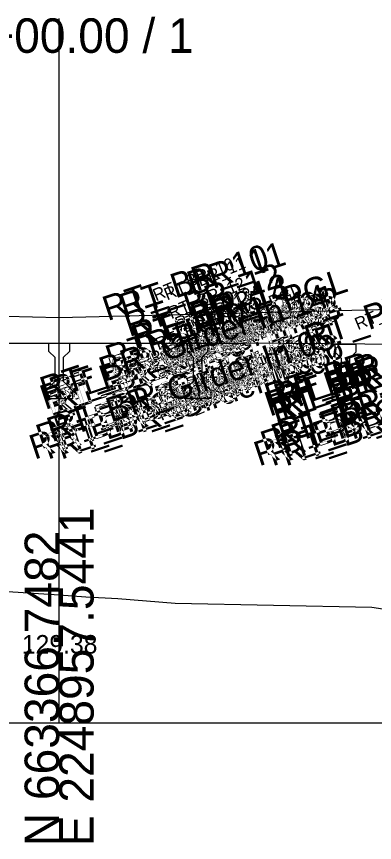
# Model space of a CAD drawing. Extents: x -26 to 2603, y -10 to 9566.
# Drawn here: x 1296.5 to 1325.6, y 3990.3 to 4057.3 of the extents above; entities that cross this region are included whole.
import ezdxf

# ---------------------------------------------------------------- set-up
doc = ezdxf.new("R2010")
doc.units = 0
for name, color, linetype in [('Exist Cross Section Cell', 7, 'Continuous'), ('Exist XS Center Line Elevation Label', 7, 'Continuous'), ('Exist XS Ground Line', 7, 'Continuous'), ('Prop CMT Concrete Structures', 7, 'Continuous'), ('Prop XS SE Text', 7, 'Continuous'), ('Scratch_Level_9', 7, 'Continuous')]:
    doc.layers.add(name, color=color, linetype=linetype)

msp = doc.modelspace()

# ---------------------------------------------------------------- linework, layer by layer
at = {"layer": 'Exist Cross Section Cell'}
for p, q in [((1300, 4000), (1300, 4057.156)), ((1000, 4000), (1300, 4000)), ((1300, 4000), (1600, 4000))]:
    msp.add_line(p, q, dxfattribs=at)
at = {"layer": 'Exist XS Ground Line'}
for p, q in [((1285.279, 4011.348), (1300, 4010.382)), ((1300, 4010.382), (1302.173, 4010.24)), ((1302.173, 4010.24), (1304.766, 4010.11)), ((1304.766, 4010.11), (1309.415, 4009.714)), ((1309.415, 4009.714), (1325.377, 4009.386)), ((1325.377, 4009.386), (1332.898, 4008.324))]:
    msp.add_line(p, q, dxfattribs=at)
at = {"layer": 'Prop CMT Concrete Structures'}
for points in [[(1299.98, 4032.865), (1284.98, 4033.24), (1272.98, 4033.54)], [(1299.98, 4032.865), (1284.98, 4033.24), (1272.98, 4033.54)], [(1299.98, 4032.865), (1284.98, 4033.24), (1272.98, 4033.54)], [(1327.003, 4033.541), (1300, 4032.866)], [(1327.003, 4033.541), (1300, 4032.866)], [(1327.003, 4033.541), (1300, 4032.866)], [(1256.499, 4030.803), (1261, 4030.803), (1285, 4030.803), (1315, 4030.803)], [(1256.499, 4030.803), (1261, 4030.803), (1285, 4030.803), (1315, 4030.803)], [(1256.499, 4030.803), (1261, 4030.803), (1285, 4030.803), (1315, 4030.803)], [(1299.167, 4030.136), (1299.167, 4030.81)], [(1299.167, 4030.81), (1300, 4030.803), (1300.833, 4030.796)], [(1299.167, 4030.136), (1299.167, 4030.81)], [(1299.167, 4030.81), (1300, 4030.803), (1300.833, 4030.796)], [(1299.167, 4030.136), (1299.167, 4030.81)], [(1299.167, 4030.81), (1300, 4030.803), (1300.833, 4030.796)], [(1300.833, 4030.796), (1300.833, 4030.136)], [(1300.833, 4030.796), (1300.833, 4030.136)], [(1300.833, 4030.796), (1300.833, 4030.136)], [(1310.41, 4030.143), (1310.41, 4030.817)], [(1310.41, 4030.817), (1311.243, 4030.81), (1312.076, 4030.803)], [(1310.41, 4030.143), (1310.41, 4030.817)], [(1310.41, 4030.817), (1311.243, 4030.81), (1312.076, 4030.803)], [(1310.41, 4030.143), (1310.41, 4030.817)], [(1310.41, 4030.817), (1311.243, 4030.81), (1312.076, 4030.803)], [(1312.076, 4030.803), (1312.076, 4030.143)], [(1312.076, 4030.803), (1312.076, 4030.143)], [(1312.076, 4030.803), (1312.076, 4030.143)], [(1385.145, 4030.219), (1351, 4030.503), (1315, 4030.803), (1315, 4030.803)], [(1385.145, 4030.219), (1351, 4030.503), (1315, 4030.803), (1315, 4030.803)], [(1386.501, 4030.207), (1351, 4030.503), (1315, 4030.803), (1315, 4030.803)], [(1322.41, 4030.741), (1323.243, 4030.734), (1324.076, 4030.727)], [(1322.41, 4030.068), (1322.41, 4030.741)], [(1322.41, 4030.741), (1323.243, 4030.734), (1324.076, 4030.727)], [(1322.41, 4030.068), (1322.41, 4030.741)], [(1322.41, 4030.741), (1323.243, 4030.734), (1324.076, 4030.727)], [(1322.41, 4030.068), (1322.41, 4030.741)], [(1324.076, 4030.727), (1324.076, 4030.068)], [(1324.076, 4030.727), (1324.076, 4030.068)], [(1324.076, 4030.727), (1324.076, 4030.068)], [(1299.667, 4029.636), (1299.167, 4030.136)], [(1299.667, 4029.636), (1299.167, 4030.136)], [(1299.667, 4029.636), (1299.167, 4030.136)], [(1300.833, 4030.136), (1300.333, 4029.636)], [(1300.833, 4030.136), (1300.333, 4029.636)], [(1300.833, 4030.136), (1300.333, 4029.636)], [(1310.91, 4029.643), (1310.41, 4030.143)], [(1310.91, 4029.643), (1310.41, 4030.143)], [(1310.91, 4029.643), (1310.41, 4030.143)], [(1312.076, 4030.143), (1311.576, 4029.643)], [(1312.076, 4030.143), (1311.576, 4029.643)], [(1312.076, 4030.143), (1311.576, 4029.643)], [(1322.91, 4029.568), (1322.41, 4030.068)], [(1322.91, 4029.568), (1322.41, 4030.068)], [(1322.91, 4029.568), (1322.41, 4030.068)], [(1324.076, 4030.068), (1323.576, 4029.568)], [(1324.076, 4030.068), (1323.576, 4029.568)], [(1324.076, 4030.068), (1323.576, 4029.568)], [(1299.667, 4027.72), (1299.667, 4029.636)], [(1299.667, 4027.72), (1299.667, 4029.636)], [(1299.667, 4027.72), (1299.667, 4029.636)], [(1300.333, 4029.636), (1300.333, 4027.72)], [(1300.333, 4029.636), (1300.333, 4027.72)], [(1300.333, 4029.636), (1300.333, 4027.72)], [(1310.91, 4027.727), (1310.91, 4029.643)], [(1310.91, 4027.727), (1310.91, 4029.643)], [(1310.91, 4027.727), (1310.91, 4029.643)], [(1311.576, 4029.643), (1311.576, 4027.727)], [(1311.576, 4029.643), (1311.576, 4027.727)], [(1311.576, 4029.643), (1311.576, 4027.727)], [(1322.91, 4027.651), (1322.91, 4029.568)], [(1322.91, 4027.651), (1322.91, 4029.568)], [(1322.91, 4027.651), (1322.91, 4029.568)], [(1323.576, 4029.568), (1323.576, 4027.651)], [(1323.576, 4029.568), (1323.576, 4027.651)], [(1323.576, 4029.568), (1323.576, 4027.651)], [(1298.917, 4026.97), (1299.667, 4027.72)], [(1298.917, 4026.97), (1299.667, 4027.72)], [(1298.917, 4026.97), (1299.667, 4027.72)], [(1300.333, 4027.72), (1301.083, 4026.97)], [(1300.333, 4027.72), (1301.083, 4026.97)], [(1300.333, 4027.72), (1301.083, 4026.97)], [(1310.16, 4026.977), (1310.91, 4027.727)], [(1310.16, 4026.977), (1310.91, 4027.727)], [(1310.16, 4026.977), (1310.91, 4027.727)], [(1311.576, 4027.727), (1312.326, 4026.977)], [(1311.576, 4027.727), (1312.326, 4026.977)], [(1311.576, 4027.727), (1312.326, 4026.977)], [(1322.16, 4026.901), (1322.91, 4027.651)], [(1322.16, 4026.901), (1322.91, 4027.651)], [(1322.16, 4026.901), (1322.91, 4027.651)], [(1323.576, 4027.651), (1324.326, 4026.901)], [(1323.576, 4027.651), (1324.326, 4026.901)], [(1323.576, 4027.651), (1324.326, 4026.901)], [(1298.917, 4026.303), (1298.917, 4026.97)], [(1298.917, 4026.303), (1298.917, 4026.97)], [(1298.917, 4026.303), (1298.917, 4026.97)], [(1301.083, 4026.97), (1301.083, 4026.303)], [(1301.083, 4026.97), (1301.083, 4026.303)], [(1301.083, 4026.97), (1301.083, 4026.303)], [(1310.16, 4026.31), (1310.16, 4026.977)], [(1310.16, 4026.31), (1310.16, 4026.977)], [(1310.16, 4026.31), (1310.16, 4026.977)], [(1312.326, 4026.977), (1312.326, 4026.31)], [(1312.326, 4026.977), (1312.326, 4026.31)], [(1312.326, 4026.977), (1312.326, 4026.31)], [(1322.16, 4026.234), (1322.16, 4026.901)], [(1322.16, 4026.234), (1322.16, 4026.901)], [(1322.16, 4026.234), (1322.16, 4026.901)], [(1324.326, 4026.901), (1324.326, 4026.234)], [(1324.326, 4026.901), (1324.326, 4026.234)], [(1324.326, 4026.901), (1324.326, 4026.234)], [(1301.083, 4026.303), (1300, 4026.303), (1298.917, 4026.303)], [(1301.083, 4026.303), (1300, 4026.303), (1298.917, 4026.303)], [(1301.083, 4026.303), (1300, 4026.303), (1298.917, 4026.303)], [(1312.326, 4026.31), (1311.243, 4026.31), (1310.16, 4026.31)], [(1312.326, 4026.31), (1311.243, 4026.31), (1310.16, 4026.31)], [(1312.326, 4026.31), (1311.243, 4026.31), (1310.16, 4026.31)], [(1324.326, 4026.234), (1323.243, 4026.234), (1322.16, 4026.234)], [(1324.326, 4026.234), (1323.243, 4026.234), (1322.16, 4026.234)], [(1324.326, 4026.234), (1323.243, 4026.234), (1322.16, 4026.234)]]:
    msp.add_lwpolyline(points, dxfattribs=at)

# ---------------------------------------------------------------- texts
at = {"layer": 'Exist Cross Section Cell'}
msp.add_text('24+00.00 / 1', height=2.8, dxfattribs=at).set_placement((1290, 4054.356))
for s, p in [('E 2248957.5441', (1302.8, 3990)), ('N 663366.7482', (1300, 3990))]:
    msp.add_text(s, height=2.8, rotation=90, dxfattribs=at).set_placement(p)
at = {"layer": 'Exist XS Center Line Elevation Label'}
msp.add_text('129.38', height=1.5, dxfattribs=at).set_placement((1296.974, 4005.632))
at = {"layer": 'Prop XS SE Text'}
msp.add_text('0.025', height=1.5, rotation=1.4321, dxfattribs=at).set_placement((1311.486, 4033.441))
at = {"layer": 'Scratch_Level_9'}
for s, height, rotation, p in [('RT_ BR_10', 2, 18.43323, (1303.944, 4032.593)), ('RT_ BR_11', 2, 18.43323, (1305.296, 4032.797)), ('RT_ BR_10', 1, 22.55745, (1307.859, 4034.194)), ('RT_ BR_11', 1, 22.55745, (1308.769, 4034.264)), ('RT_BR_12', 2, 18.43323, (1305.702, 4031.293)), ('RT_PV1_PGL', 2, 18.43323, (1307.473, 4029.678)), ('RT_PV1_CP', 2, 18.43323, (1320.324, 4030.261)), ('RT_BR_13', 2, 18.43323, (1306.285, 4030.46)), ('RT_BR_14', 2, 18.43323, (1306.295, 4030.21)), ('RT_BR_12', 1, 22.55745, (1309.104, 4032.751)), ('RT_BR_Girder In 14', 2, 18.43323, (1298.869, 4026.065)), ('RT_BR_Girder In 01', 2, 18.43323, (1299.628, 4026.033)), ('RT_BR_Girder In 02', 2, 18.43323, (1299.923, 4025.847)), ('RT_BR_13', 1, 22.55745, (1309.672, 4031.911)), ('RT_PV1_PGL', 1, 22.55745, (1311.906, 4031.414)), ('RT_BR_Girder Mid 14', 2, 18.43323, (1317.095, 4025.52)), ('RT_BR_Girder Mid 01', 2, 18.43323, (1317.853, 4025.488)), ('RT_BR_Girder Mid 02', 2, 18.43323, (1318.149, 4025.302)), ('RT_PV1_CP', 1, 22.55745, (1324.249, 4031.857)), ('RT_BR_Girder In 13', 2, 18.43323, (1298.869, 4025.391)), ('RT_BR_Girder In 03', 2, 18.43323, (1299.923, 4025.187)), ('RT_BR_14', 1, 22.55745, (1309.667, 4031.655)), ('RT_BR_Girder Mid 13', 2, 18.43323, (1317.095, 4024.846)), ('RT_BR_Girder Mid 03', 2, 18.43323, (1318.149, 4024.642)), ('RT_BR_Girder In 12', 2, 18.43323, (1299.369, 4024.891)), ('RT_BR_Girder In 04', 2, 18.43323, (1299.423, 4024.687)), ('RT_BR_09', 2, 18.43323, (1304.182, 4028.618)), ('RT_BR_Girder In 14', 1, 22.55745, (1307.576, 4029.052)), ('RT_BR_Girder In 01', 1, 22.55745, (1308.463, 4029.067)), ('RT_BR_08', 2, 18.43323, (1308.683, 4028.581)), ('RT_BR_Girder In 02', 1, 22.55745, (1309.162, 4029.004)), ('RT_BR_Girder Mid 12', 2, 18.43323, (1317.595, 4024.346)), ('RT_BR_Girder Mid 04', 2, 18.43323, (1317.649, 4024.142)), ('RT_BR_Girder In 13', 1, 22.55745, (1307.591, 4028.384)), ('RT_BR_09', 1, 22.55745, (1308.061, 4030.224)), ('RT_BR_Girder In 12', 1, 22.55745, (1308.106, 4027.89)), ('RT_BR_Girder In 04', 1, 22.55745, (1308.632, 4027.832)), ('RT_BR_Girder In 03', 1, 22.55745, (1309.147, 4028.338)), ('RT_BR_08', 1, 22.55745, (1312.558, 4030.185)), ('RT_BR_Girder Mid 11', 2, 18.43323, (1318.132, 4022.609)), ('RT_BR_Girder In 05', 2, 18.43323, (1299.423, 4022.77)), ('RT_BR_Girder In 11', 2, 18.43323, (1299.907, 4023.154)), ('RT_BR_Girder Mid 05', 2, 18.43323, (1317.649, 4022.225)), ('RT_BR_Girder In 10', 2, 18.43323, (1298.544, 4022.2)), ('RT_BR_Girder In 06', 2, 18.43323, (1300.128, 4022.005)), ('RT_BR_Girder In 11', 1, 22.55745, (1308.24, 4026.029)), ('RT_BR_Girder In 05', 1, 22.55745, (1308.641, 4025.919)), ('RT_BR_Girder Mid 10', 2, 18.43323, (1316.77, 4021.655)), ('RT_BR_Girder Mid 06', 2, 18.43323, (1318.354, 4021.46)), ('RT_BR_Girder In 09', 2, 18.43323, (1298.006, 4021.354)), ('RT_BR_Girder In 08', 2, 18.43323, (1299.09, 4021.354)), ('RT_BR_Girder In 07', 2, 18.43323, (1300.173, 4021.354)), ('RT_BR_Girder In 10', 1, 22.55745, (1307.32, 4025.209)), ('RT_BR_Girder In 06', 1, 22.55745, (1309.385, 4025.167)), ('RT_BR_Girder Mid 09', 2, 18.43323, (1316.232, 4020.809)), ('RT_BR_Girder Mid 08', 2, 18.43323, (1317.315, 4020.809)), ('RT_BR_Girder Mid 07', 2, 18.43323, (1318.399, 4020.809)), ('RT_BR_Girder In 09', 1, 22.55745, (1307.221, 4024.501)), ('RT_BR_Girder In 08', 1, 22.55745, (1308.301, 4024.499)), ('RT_BR_Girder In 07', 1, 22.55745, (1309.372, 4024.494))]:
    msp.add_text(s, height=height, rotation=rotation, dxfattribs=at).set_placement(p)

doc.saveas('drawing.dxf')
